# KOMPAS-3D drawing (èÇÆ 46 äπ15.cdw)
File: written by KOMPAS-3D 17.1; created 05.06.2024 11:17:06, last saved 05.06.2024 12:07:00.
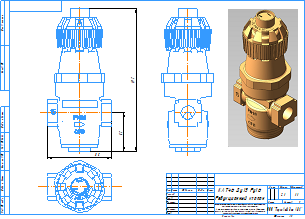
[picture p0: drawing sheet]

Sheet 1: A3, landscape

Title block, sheet 1: name: КАТ46 Ду15 Ру16 / Редукционный клапан; material: Внимание! Данный продукт является объектом авторского права ООО «Торговый Дом АДЛ». / Запрещается изменение, копирование, распространение / (в том числе путем копирования на другие сайты и ресурсы в Интернете) / или любое иное использование информации и объектов без предварительного / согласия правообладателя (ООО «Торговый Дом АДЛ»).; mass: 2,1; sheets: 1; organisation: ООО "Торговый дом АДЛ"; sheet format: A3; stored path: C:\Users\klav\Desktop\Модели\0 КАТ\КАТ 46\KOMPAS 3D\КАТ 46 Ду25.cdw

Views: Вид 1, Спереди, Проекционный вид 2
Referenced files in C:\Users\klav\Desktop\Модели\0 КАТ\КАТ 46\KOMPAS 3D\: КАТ 46 Ду25.m3d, КАТ 46 Ду15.m3d
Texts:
  Клочков АВ
  ООО АДЛ Групп
  КАТ 46 Ду15
Dimensions and other numbers on the sheet: 85; 52; 192; 1:1; 1; 2,1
